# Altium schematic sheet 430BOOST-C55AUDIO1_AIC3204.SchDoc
size A4; PageSetup: Record=PageOptions|CenterHorizontal=True|CenterVertical=True|PrintScale=1.00|XCorrection=1.00|YCorrection=1.00|PrintKind=0|BorderSize=5000000|LeftOffset=0|BottomOffset=0|Orientation=2|PaperLength=1000|PaperWidth=1000|Scale=100|PaperSource=7|PrintQuality=-4|MediaType=1|DitherType=10|PaperKind=A4|PrintScaleMode=1
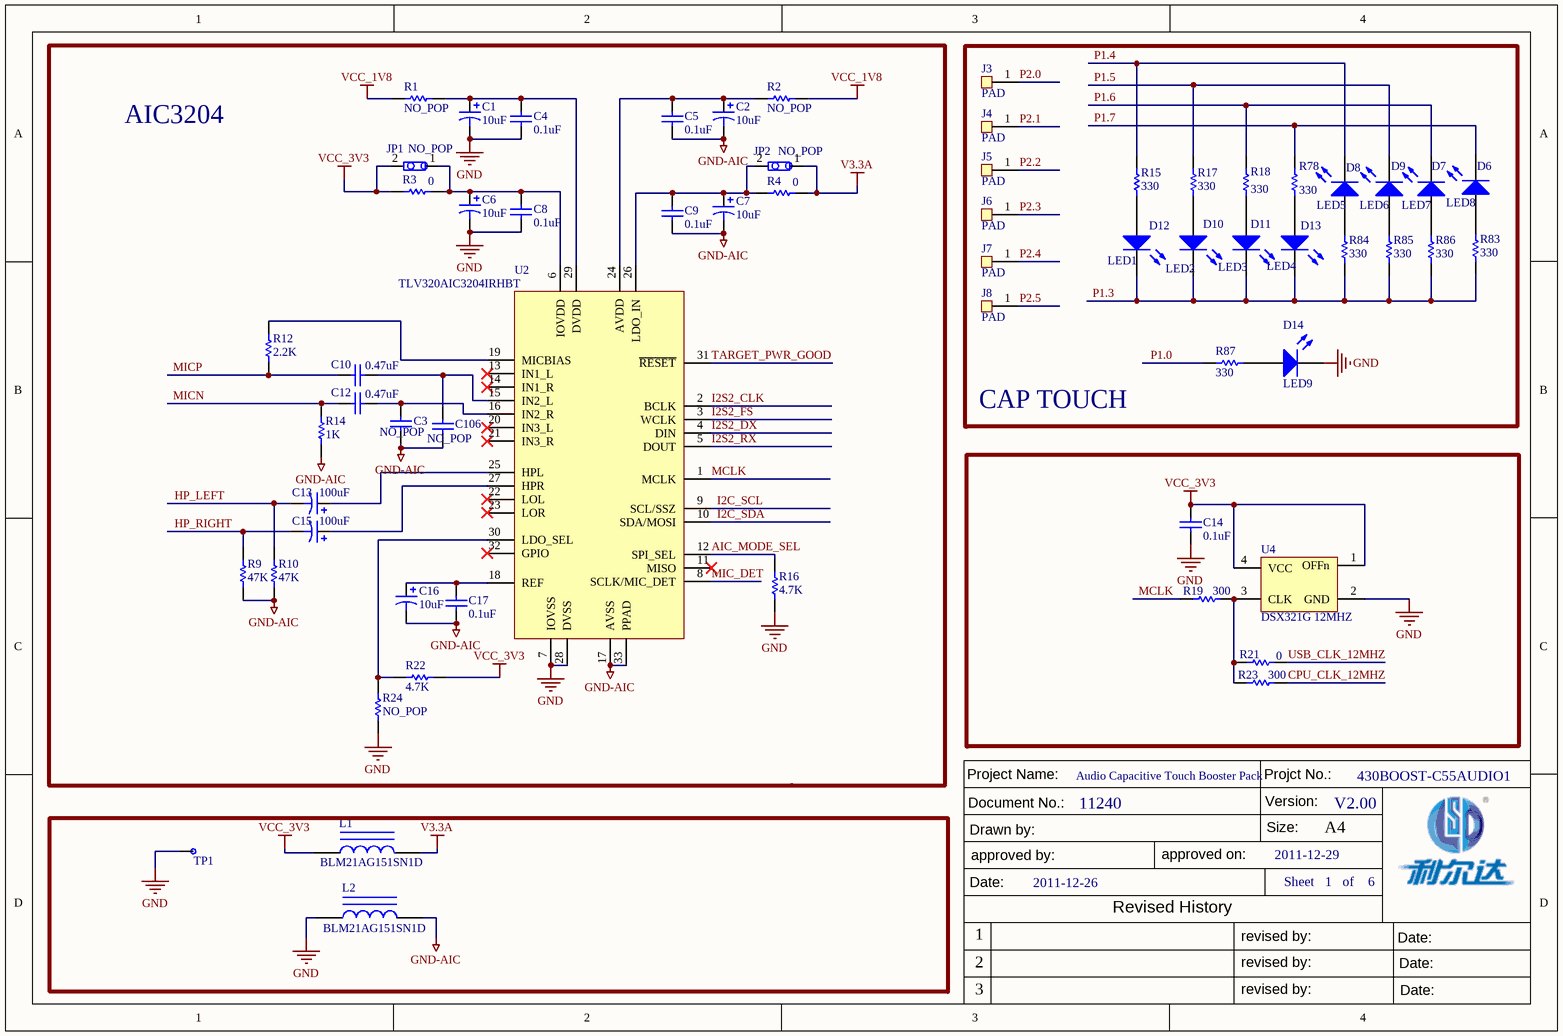
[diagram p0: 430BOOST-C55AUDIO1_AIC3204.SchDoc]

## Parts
C1  10uF  [0805-c]
C2  10uF  [0805-c]
C3  NO_POP  [0402-C]
C4  0.1uF  [0402-C]
C5  0.1uF  [0402-C]
C6  10uF  [0805-c]
C7  10uF  [0805-c]
C8  0.1uF  [0402-C]
C9  0.1uF  [0402-C]
C10  0.47uF  [0402-C]
C12  0.47uF  [0402-C]
C13  100uF  [SMD-C]
C14  0.1uF  [0402-C]
C15  100uF  [SMD-C]
C16  10uF  [0805-c]
C17  0.1uF  [0402-C]
C106  NO_POP  [0402-C]
D6  LED8  [1206-W]
D7  LED7  [1206-W]
D8  LED5  [1206-W]
D9  LED6  [1206-W]
D10  LED2  [1206-W]
D11  LED3  [1206-W]
D12  LED1  [1206-W]
D13  LED4  [1206-W]
D14  LED9  [1206-W]
J3  PAD  [SIP1-TEST]
J4  PAD  [SIP1-TEST]
J5  PAD  [SIP1-TEST]
J6  PAD  [SIP1-TEST]
J7  PAD  [SIP1-TEST]
J8  PAD  [SIP1-TEST]
JP1  NO_POP  [SIP2-2.54]
JP2  NO_POP  [SIP2-2.54]
L1  BLM21AG151SN1D  [0603-L]
L2  BLM21AG151SN1D  [0603-L]
R1  NO_POP  [0402-R]
R2  NO_POP  [0402-R]
R3  0  [0402-R]
R4  0  [0402-R]
R9  47K  [0402-R]
R10  47K  [0402-R]
R12  2.2K  [0402-R]
R14  1K  [0402-R]
R15  330  [0402-R]
R16  4.7K  [0402-R]
R17  330  [0402-R]
R18  330  [0402-R]
R19  300  [0402-R]
R21  0  [0402-R]
R22  4.7K  [0402-R]
R23  300  [0402-R]
R24  NO_POP  [0402-R]
R78  330  [0402-R]
R83  330  [0402-R]
R84  330  [0402-R]
R85  330  [0402-R]
R86  330  [0402-R]
R87  330  [0402-R]
TP1  GND  [SIP1-TEST]  (value not drawn)
U2  TLV320AIC3204IRHBT  [QFN-32P-0.5MM]
U4  DSX321G 12MHZ  [SMD3225-4]

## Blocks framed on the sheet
AIC3204: C1-C10 C12 C13 C15-C17 C106 JP1 JP2 R1-R4 R9 R10 R12 R14 R16 R22 R24 U2
CAP TOUCH: D6-D14 J3-J8 R15 R17 R18 R78 R83-R87

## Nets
GND: C1.2 C4.1 C6.2 C8.1 C14.1 D14.2(K) L2.1 R16.1 R24.2 TP1.1 U2.7(IOVSS) U2.28(DVSS) U4.2(GND)
GND-AIC: C2.2 C3.1 C5.1 C7.2 C9.1 C16.2 C17.1 C106.1 L2.2 R9.1 R10.1 R14.1 U2.17(AVSS) U2.33(PPAD)
V3.3A: JP2.1 L1.2 R4.2
VCC_1V8: R1.1 R2.2
VCC_3V3: C14.2 JP1.2 L1.1 R3.1 R22.1 U4.1(OFFn) U4.4(VCC)
AIC_MODE_SEL: R16.2 U2.12(SPI_SEL)
CPU_CLK_12MHZ: R23.2
HP_LEFT: C13.2 R10.2
HP_RIGHT: C15.2 R9.2
I2C_SCL: U2.9(SCL/SSZ)
I2C_SDA: U2.10(SDA/MOSI)
I2S2_CLK: U2.2(BCLK)
I2S2_DX: U2.4(DIN)
I2S2_FS: U2.3(WCLK)
I2S2_RX: U2.5(DOUT)
MCLK: R19.1 U2.1(MCLK)
MIC_DET: U2.8(SCLK/MIC_DET)
MICN: C12.2 R14.2
MICP: C10.2 R12.1
P1.0: R87.2
P1.3: D10.2(K) D11.2(K) D12.2(K) D13.2(K) R83.1 R84.1 R85.1 R86.1
P1.4: D8.2(K) R15.2
P1.5: D9.2(K) R17.2
P1.6: D7.2(K) R18.2
P1.7: D6.2(K) R78.2
P2.0: J3.1
P2.1: J4.1
P2.2: J5.1
P2.3: J6.1
P2.4: J7.1
P2.5: J8.1
TARGET_PWR_GOOD: U2.31(~{RESET})
USB_CLK_12MHZ: R21.2
NetC1_1: C1.1 C4.2 R1.2 U2.29(DVDD)
NetC2_1: C2.1 C5.2 R2.1 U2.24(AVDD)
NetC3_2: C3.2 C12.1 U2.16(IN2_R)
NetC6_1: C6.1 C8.2 JP1.1 R3.2 U2.6(IOVDD)
NetC7_1: C7.1 C9.2 JP2.2 R4.1 U2.26(LDO_IN)
NetC10_1: C10.1 C106.2 U2.15(IN2_L)
NetC13_1: C13.1 U2.25(HPL)
NetC15_1: C15.1 U2.27(HPR)
NetC16_1: C16.1 C17.2 U2.18(REF)
NetD6_1: D6.1(A) R83.2
NetD7_1: D7.1(A) R86.2
NetD8_1: D8.1(A) R84.2
NetD9_1: D9.1(A) R85.2
NetD10_1: D10.1(A) R17.1
NetD11_1: D11.1(A) R18.1
NetD12_1: D12.1(A) R15.1
NetD13_1: D13.1(A) R78.1
NetD14_1: D14.1(A) R87.1
NetR12_2: R12.2 U2.19(MICBIAS)
NetR19_2: R19.2 R21.1 R23.1 U4.3(CLK)
NetR22_2: R22.2 R24.1 U2.30(LDO_SEL)

Not connected (* = marked no-connect by the designer): U2 11(MISO)* 13(IN1_L)* 14(IN1_R)* 20(IN3_L)* 21(IN3_R)* 22(LOL)* 23(LOR)* 32(GPIO)*

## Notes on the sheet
- Audio Capacitive Touch Booster Pack
- 430BOOST-C55AUDIO1
- 11240
- V2.00
- 2011-12-26
- 2011-12-29
- Sheet   1   of    6

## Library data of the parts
C1 C2 C6 C7 C13 C15 C16 = Cap Pol1: Polarized Capacitor (Radial); Value: 100pF
C3-C5 C8-C10 C12 C14 C17 C106 = Cap: Capacitor; Value: 100pF
D6-D14 = LED0: Typical INFRARED GaAs LED
JP1 JP2 = JUMPER
L1 L2 = Inductor Iron: Magnetic-Core Inductor; Value: 10mH
R1-R4 R9 R10 R12 R15-R19 R21-R24 R78 R83-R87 = Res1: Resistor; Value: 1K
R14 = Res1: Resistor
TP1 = TextPoint
U4 = ASDM1-12.000MHZ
